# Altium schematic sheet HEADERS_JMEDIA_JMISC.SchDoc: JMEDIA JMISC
size A3; Author: Silvio Navaretti; CompanyName: ARDUINO; DrawnBy: Silvio Navaretti; Engineer: Silvio Navaretti; Organization: ARDUINO; SheetNumber: 21; SheetTotal: 51; RevAuthor: Silvio Navaretti
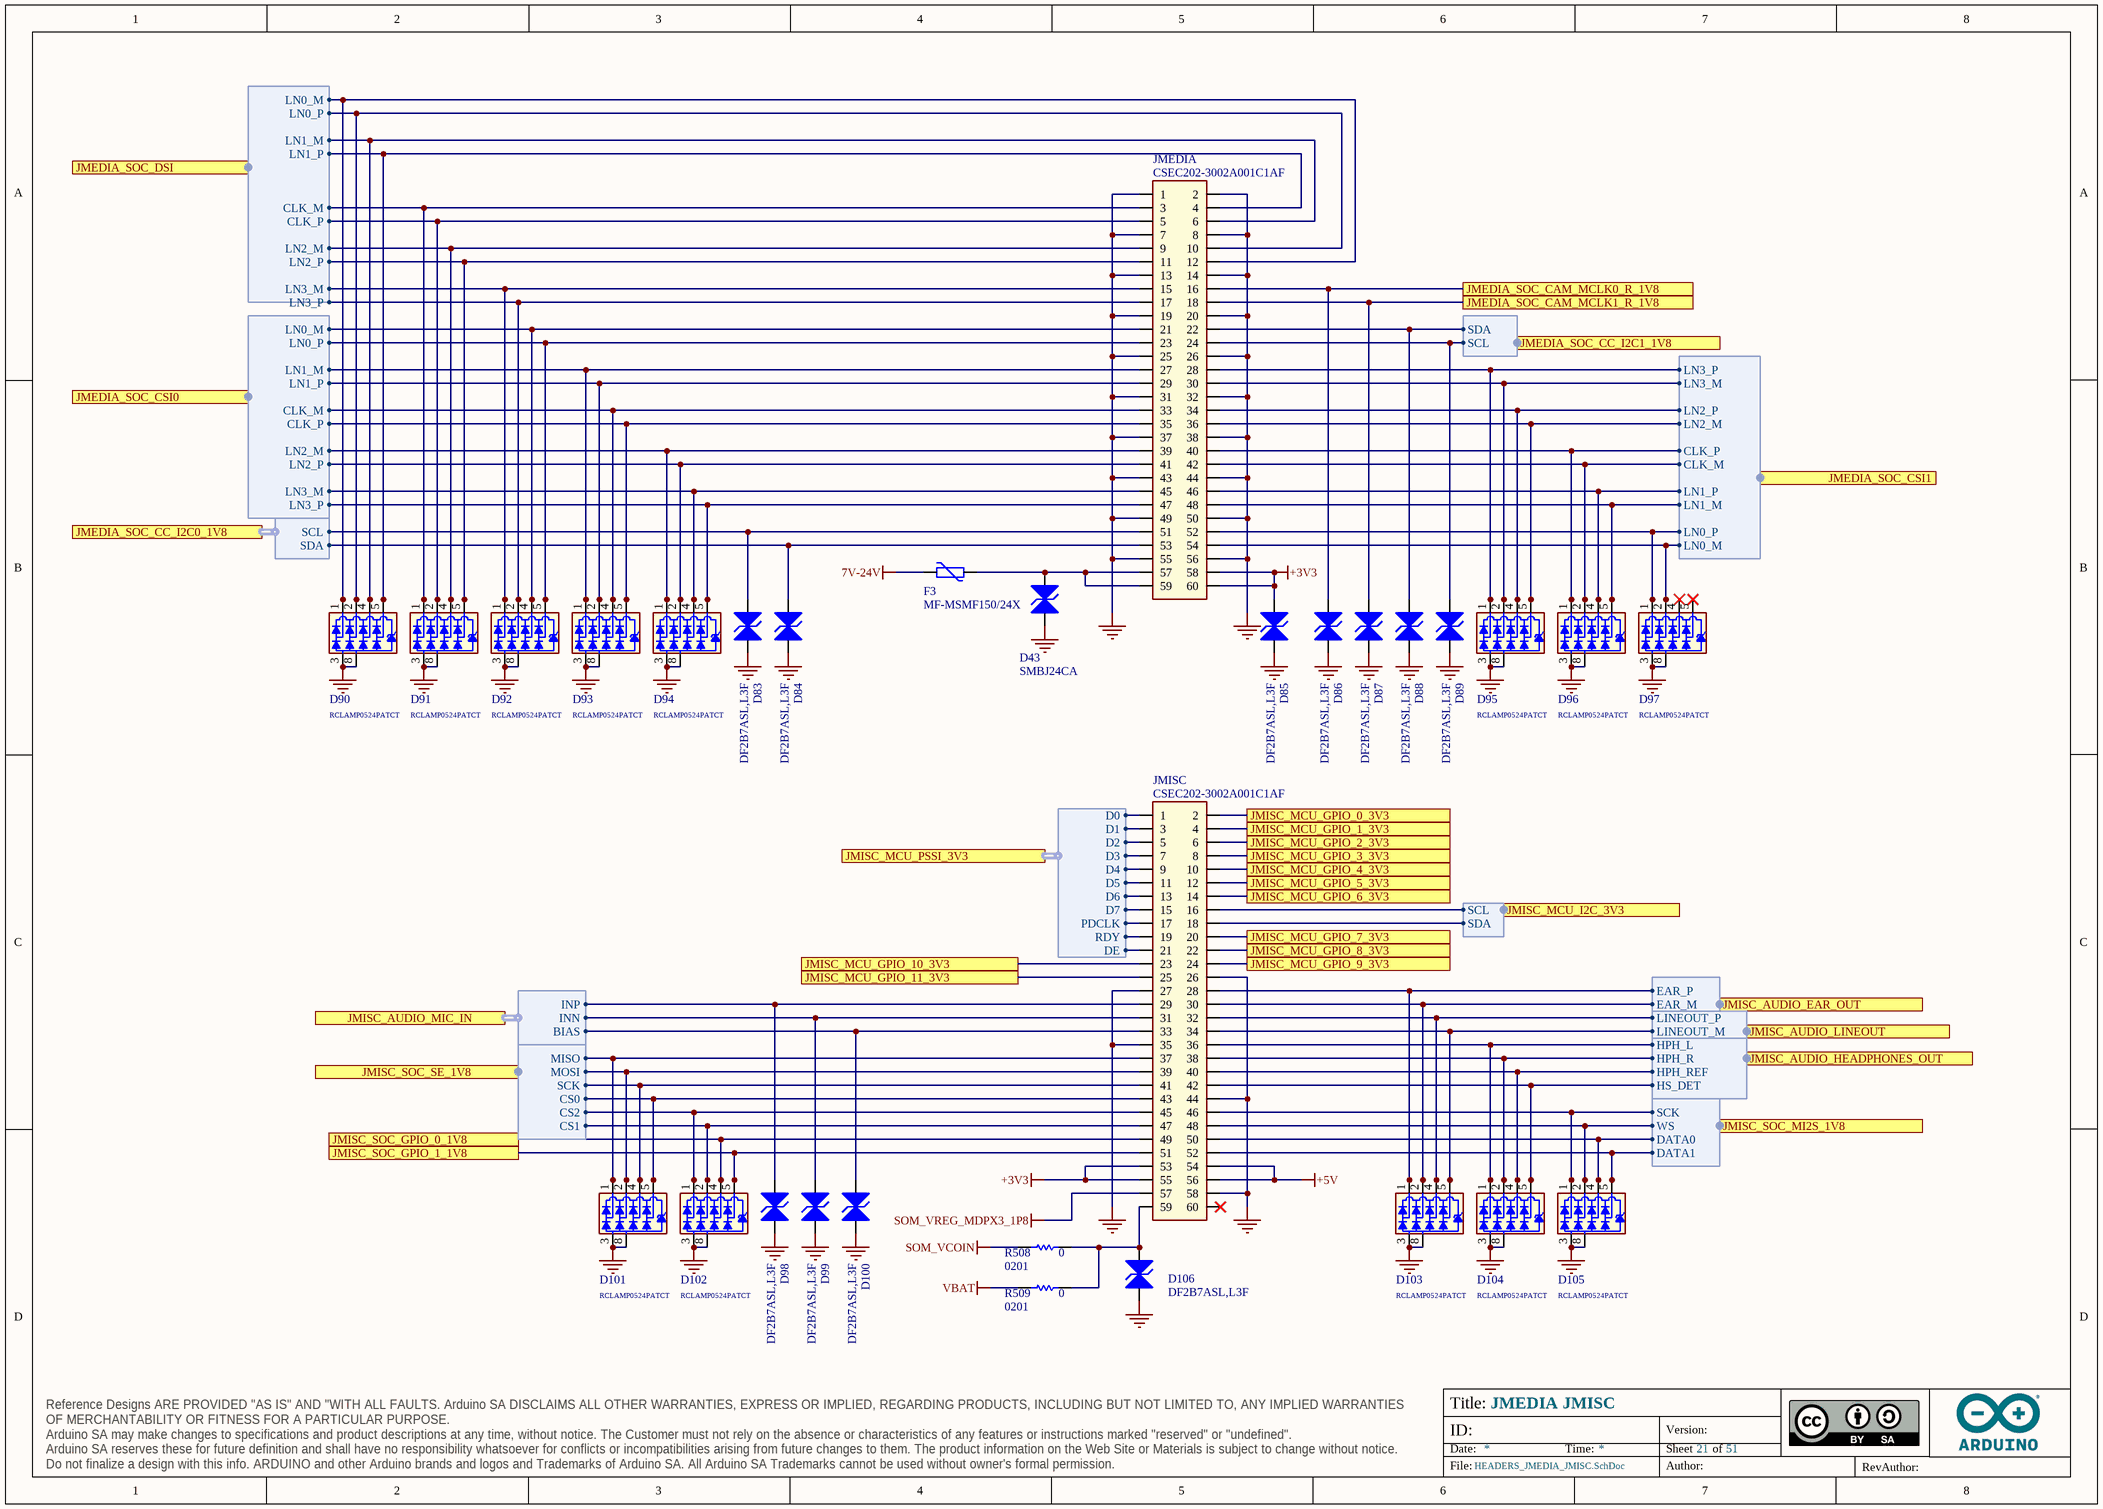
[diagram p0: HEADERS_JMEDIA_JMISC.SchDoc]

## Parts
D43  SMBJ24CA  [SMB_NOPOLARITY]
D83  DF2B7ASL,L3F  [DF2B7ASL,L3F]
D84  DF2B7ASL,L3F  [DF2B7ASL,L3F]
D85  DF2B7ASL,L3F  [DF2B7ASL,L3F]
D86  DF2B7ASL,L3F  [DF2B7ASL,L3F]
D87  DF2B7ASL,L3F  [DF2B7ASL,L3F]
D88  DF2B7ASL,L3F  [DF2B7ASL,L3F]
D89  DF2B7ASL,L3F  [DF2B7ASL,L3F]
D90  RCLAMP0524PATCT  [SLP2510P8]
D91  RCLAMP0524PATCT  [SLP2510P8]
D92  RCLAMP0524PATCT  [SLP2510P8]
D93  RCLAMP0524PATCT  [SLP2510P8]
D94  RCLAMP0524PATCT  [SLP2510P8]
D95  RCLAMP0524PATCT  [SLP2510P8]
D96  RCLAMP0524PATCT  [SLP2510P8]
D97  RCLAMP0524PATCT  [SLP2510P8]
D98  DF2B7ASL,L3F  [DF2B7ASL,L3F]
D99  DF2B7ASL,L3F  [DF2B7ASL,L3F]
D100  DF2B7ASL,L3F  [DF2B7ASL,L3F]
D101  RCLAMP0524PATCT  [SLP2510P8]
D102  RCLAMP0524PATCT  [SLP2510P8]
D103  RCLAMP0524PATCT  [SLP2510P8]
D104  RCLAMP0524PATCT  [SLP2510P8]
D105  RCLAMP0524PATCT  [SLP2510P8]
D106  DF2B7ASL,L3F  [DF2B7ASL,L3F]
F3  MF-MSMF150/24X  [1812]
JMEDIA  CSEC202-3002A001C1AF  [CSEC202-3002A001C1AF]
JMISC  CSEC202-3002A001C1AF  [CSEC202-3002A001C1AF]
R508  value 0  Case Code (Imperial): 0201  [RES-0201]  (hidden comment: CRCW02010000Z0ED)
R509  value 0  Case Code (Imperial): 0201  [RES-0201]  (hidden comment: CRCW02010000Z0ED)

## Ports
JMEDIA_SOC_CAM_MCLK0_R_1V8, JMEDIA_SOC_CAM_MCLK1_R_1V8, JMEDIA_SOC_CC_I2C0_1V8 (harness I2C), JMEDIA_SOC_CC_I2C1_1V8 (harness I2C), JMEDIA_SOC_CSI0 (harness MIPI_4LANES), JMEDIA_SOC_CSI1 (harness MIPI_4LANES), JMEDIA_SOC_DSI (harness MIPI_4LANES), JMISC_AUDIO_EAR_OUT (harness EAT), JMISC_AUDIO_HEADPHONES_OUT (harness HEADPHONES), JMISC_AUDIO_LINEOUT (harness LINEOUT), JMISC_AUDIO_MIC_IN (harness MIC), JMISC_MCU_GPIO_0_3V3, JMISC_MCU_GPIO_1_3V3, JMISC_MCU_GPIO_2_3V3, JMISC_MCU_GPIO_3_3V3, JMISC_MCU_GPIO_4_3V3, JMISC_MCU_GPIO_5_3V3, JMISC_MCU_GPIO_6_3V3, JMISC_MCU_GPIO_7_3V3, JMISC_MCU_GPIO_8_3V3, JMISC_MCU_GPIO_9_3V3, JMISC_MCU_GPIO_10_3V3, JMISC_MCU_GPIO_11_3V3, JMISC_MCU_I2C_3V3 (harness I2C), JMISC_MCU_PSSI_3V3 (harness PSSI), JMISC_SOC_GPIO_0_1V8, JMISC_SOC_GPIO_1_1V8, JMISC_SOC_MI2S_1V8 (harness SOM_MD_I2S), JMISC_SOC_SE_1V8 (harness SOM_MD_SPI_3CS)

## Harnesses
MIPI_4LANES: LN3_M, LN2_M, LN2_P, LN0_M, LN0_P, CLK_M, CLK_P, LN1_M, LN1_P, LN3_P
I2C: SDA, SCL
EAT: EAR_P, EAR_M
MIC: INP, INN, BIAS
LINEOUT: LINEOUT_P, LINEOUT_M
HEADPHONES: HPH_L, HPH_R, HPH_REF, HS_DET
SOM_MD_SPI_3CS: SCK, MISO, MOSI, CS0, CS1, CS2
SOM_MD_I2S: SCK, WS, DATA0, DATA1
PSSI: D0, D1, D2, D3, D4, D5, D6, D7, PDCLK, RDY, DE

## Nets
7V-24V: F3.1
+3V3: D85.2(A2) JMEDIA.58 JMEDIA.60 JMISC.53 JMISC.55
+5V: JMISC.54 JMISC.56
GND: D43.1(A1) D83.1(A1) D84.1(A1) D85.1(A1) D86.1(A1) D87.1(A1) D88.1(A1) D89.1(A1) D90.3 D90.8 D91.3 D91.8 D92.3 D92.8 D93.3 D93.8 D94.3 D94.8 D95.3 D95.8 D96.3 D96.8 D97.3 D97.8 D98.1(A1) D99.1(A1) D100.1(A1) D101.3 D101.8 D102.3 D102.8 D103.3 D103.8 D104.3 D104.8 D105.3 D105.8 D106.1(A1) JMEDIA.1 JMEDIA.2 JMEDIA.7 JMEDIA.8 JMEDIA.13 JMEDIA.14 JMEDIA.19 JMEDIA.20 JMEDIA.25 JMEDIA.26 JMEDIA.31 JMEDIA.32 JMEDIA.37 JMEDIA.38 JMEDIA.43 JMEDIA.44 JMEDIA.49 JMEDIA.50 JMEDIA.55 JMEDIA.56 JMISC.26 JMISC.27 JMISC.35 JMISC.44 JMISC.58
SOM_VCOIN: R508.2
SOM_VREG_MDPX3_1P8: JMISC.57
VBAT: R509.2
JMEDIA_SOC_CAM_MCLK0_R_1V8: D86.2(A2) JMEDIA.16 ; port JMEDIA_SOC_CAM_MCLK0_R_1V8
JMEDIA_SOC_CAM_MCLK1_R_1V8: D87.2(A2) JMEDIA.18 ; port JMEDIA_SOC_CAM_MCLK1_R_1V8
JMISC_MCU_GPIO_0_3V3: JMISC.2 ; port JMISC_MCU_GPIO_0_3V3
JMISC_MCU_GPIO_1_3V3: JMISC.4 ; port JMISC_MCU_GPIO_1_3V3
JMISC_MCU_GPIO_2_3V3: JMISC.6 ; port JMISC_MCU_GPIO_2_3V3
JMISC_MCU_GPIO_3_3V3: JMISC.8 ; port JMISC_MCU_GPIO_3_3V3
JMISC_MCU_GPIO_4_3V3: JMISC.10 ; port JMISC_MCU_GPIO_4_3V3
JMISC_MCU_GPIO_5_3V3: JMISC.12 ; port JMISC_MCU_GPIO_5_3V3
JMISC_MCU_GPIO_6_3V3: JMISC.14 ; port JMISC_MCU_GPIO_6_3V3
JMISC_MCU_GPIO_7_3V3: JMISC.20 ; port JMISC_MCU_GPIO_7_3V3
JMISC_MCU_GPIO_8_3V3: JMISC.22 ; port JMISC_MCU_GPIO_8_3V3
JMISC_MCU_GPIO_9_3V3: JMISC.24 ; port JMISC_MCU_GPIO_9_3V3
JMISC_MCU_GPIO_10_3V3: JMISC.23 ; port JMISC_MCU_GPIO_10_3V3
JMISC_MCU_GPIO_11_3V3: JMISC.25 ; port JMISC_MCU_GPIO_11_3V3
JMISC_SOC_GPIO_0_1V8: D102.4 D102.7 JMISC.49 ; port JMISC_SOC_GPIO_0_1V8
JMISC_SOC_GPIO_1_1V8: D102.5 D102.6 JMISC.51 ; port JMISC_SOC_GPIO_1_1V8
NetD43_2: D43.2(A2) F3.2 JMEDIA.57 JMEDIA.59
NetD83_2: D83.2(A2) JMEDIA.51 ; port JMEDIA_SOC_CC_I2C0_1V8.SCL
NetD84_2: D84.2(A2) JMEDIA.53 ; port JMEDIA_SOC_CC_I2C0_1V8.SDA
NetD88_2: D88.2(A2) JMEDIA.22 ; port JMEDIA_SOC_CC_I2C1_1V8.SDA
NetD89_2: D89.2(A2) JMEDIA.24 ; port JMEDIA_SOC_CC_I2C1_1V8.SCL
NetD90_1: D90.1 D90.10 JMEDIA.12 ; port JMEDIA_SOC_DSI.LN0_M
NetD90_2: D90.2 D90.9 JMEDIA.10 ; port JMEDIA_SOC_DSI.LN0_P
NetD90_4: D90.4 D90.7 JMEDIA.6 ; port JMEDIA_SOC_DSI.LN1_M
NetD90_5: D90.5 D90.6 JMEDIA.4 ; port JMEDIA_SOC_DSI.LN1_P
NetD91_1: D91.1 D91.10 JMEDIA.3 ; port JMEDIA_SOC_DSI.CLK_M
NetD91_2: D91.2 D91.9 JMEDIA.5 ; port JMEDIA_SOC_DSI.CLK_P
NetD91_4: D91.4 D91.7 JMEDIA.9 ; port JMEDIA_SOC_DSI.LN2_M
NetD91_5: D91.5 D91.6 JMEDIA.11 ; port JMEDIA_SOC_DSI.LN2_P
NetD92_1: D92.1 D92.10 JMEDIA.15 ; port JMEDIA_SOC_DSI.LN3_M
NetD92_2: D92.2 D92.9 JMEDIA.17 ; port JMEDIA_SOC_DSI.LN3_P
NetD92_4: D92.4 D92.7 JMEDIA.21 ; port JMEDIA_SOC_CSI0.LN0_M
NetD92_5: D92.5 D92.6 JMEDIA.23 ; port JMEDIA_SOC_CSI0.LN0_P
NetD93_1: D93.1 D93.10 JMEDIA.27 ; port JMEDIA_SOC_CSI0.LN1_M
NetD93_2: D93.2 D93.9 JMEDIA.29 ; port JMEDIA_SOC_CSI0.LN1_P
NetD93_4: D93.4 D93.7 JMEDIA.33 ; port JMEDIA_SOC_CSI0.CLK_M
NetD93_5: D93.5 D93.6 JMEDIA.35 ; port JMEDIA_SOC_CSI0.CLK_P
NetD94_1: D94.1 D94.10 JMEDIA.39 ; port JMEDIA_SOC_CSI0.LN2_M
NetD94_2: D94.2 D94.9 JMEDIA.41 ; port JMEDIA_SOC_CSI0.LN2_P
NetD94_4: D94.4 D94.7 JMEDIA.45 ; port JMEDIA_SOC_CSI0.LN3_M
NetD94_5: D94.5 D94.6 JMEDIA.47 ; port JMEDIA_SOC_CSI0.LN3_P
NetD95_1: D95.1 D95.10 JMEDIA.28 ; port JMEDIA_SOC_CSI1.LN3_P
NetD95_2: D95.2 D95.9 JMEDIA.30 ; port JMEDIA_SOC_CSI1.LN3_M
NetD95_4: D95.4 D95.7 JMEDIA.34 ; port JMEDIA_SOC_CSI1.LN2_P
NetD95_5: D95.5 D95.6 JMEDIA.36 ; port JMEDIA_SOC_CSI1.LN2_M
NetD96_1: D96.1 D96.10 JMEDIA.40 ; port JMEDIA_SOC_CSI1.CLK_P
NetD96_2: D96.2 D96.9 JMEDIA.42 ; port JMEDIA_SOC_CSI1.CLK_M
NetD96_4: D96.4 D96.7 JMEDIA.46 ; port JMEDIA_SOC_CSI1.LN1_P
NetD96_5: D96.5 D96.6 JMEDIA.48 ; port JMEDIA_SOC_CSI1.LN1_M
NetD97_1: D97.1 D97.10 JMEDIA.52 ; port JMEDIA_SOC_CSI1.LN0_P
NetD97_2: D97.2 D97.9 JMEDIA.54 ; port JMEDIA_SOC_CSI1.LN0_M
NetD97_4: D97.4 D97.7
NetD97_5: D97.5 D97.6
NetD98_2: D98.2(A2) JMISC.29 ; port JMISC_AUDIO_MIC_IN.INP
NetD99_2: D99.2(A2) JMISC.31 ; port JMISC_AUDIO_MIC_IN.INN
NetD100_2: D100.2(A2) JMISC.33 ; port JMISC_AUDIO_MIC_IN.BIAS
NetD101_1: D101.1 D101.10 JMISC.37 ; port JMISC_SOC_SE_1V8.MISO
NetD101_2: D101.2 D101.9 JMISC.39 ; port JMISC_SOC_SE_1V8.MOSI
NetD101_4: D101.4 D101.7 JMISC.41 ; port JMISC_SOC_SE_1V8.SCK
NetD101_5: D101.5 D101.6 JMISC.43 ; port JMISC_SOC_SE_1V8.CS0
NetD102_1: D102.1 D102.10 JMISC.45 ; port JMISC_SOC_SE_1V8.CS2
NetD102_2: D102.2 D102.9 JMISC.47 ; port JMISC_SOC_SE_1V8.CS1
NetD103_1: D103.1 D103.10 JMISC.28 ; port JMISC_AUDIO_EAR_OUT.EAR_P
NetD103_2: D103.2 D103.9 JMISC.30 ; port JMISC_AUDIO_EAR_OUT.EAR_M
NetD103_4: D103.4 D103.7 JMISC.32 ; port JMISC_AUDIO_LINEOUT.LINEOUT_P
NetD103_5: D103.5 D103.6 JMISC.34 ; port JMISC_AUDIO_LINEOUT.LINEOUT_M
NetD104_1: D104.1 D104.10 JMISC.36 ; port JMISC_AUDIO_HEADPHONES_OUT.HPH_L
NetD104_2: D104.2 D104.9 JMISC.38 ; port JMISC_AUDIO_HEADPHONES_OUT.HPH_R
NetD104_4: D104.4 D104.7 JMISC.40 ; port JMISC_AUDIO_HEADPHONES_OUT.HPH_REF
NetD104_5: D104.5 D104.6 JMISC.42 ; port JMISC_AUDIO_HEADPHONES_OUT.HS_DET
NetD105_1: D105.1 D105.10 JMISC.46 ; port JMISC_SOC_MI2S_1V8.SCK
NetD105_2: D105.2 D105.9 JMISC.48 ; port JMISC_SOC_MI2S_1V8.WS
NetD105_4: D105.4 D105.7 JMISC.50 ; port JMISC_SOC_MI2S_1V8.DATA0
NetD105_5: D105.5 D105.6 JMISC.52 ; port JMISC_SOC_MI2S_1V8.DATA1
NetD106_2: D106.2(A2) JMISC.59 R508.1 R509.1
NetJMISC_1: JMISC.1 ; port JMISC_MCU_PSSI_3V3.D0
NetJMISC_3: JMISC.3 ; port JMISC_MCU_PSSI_3V3.D1
NetJMISC_5: JMISC.5 ; port JMISC_MCU_PSSI_3V3.D2
NetJMISC_7: JMISC.7 ; port JMISC_MCU_PSSI_3V3.D3
NetJMISC_9: JMISC.9 ; port JMISC_MCU_PSSI_3V3.D4
NetJMISC_11: JMISC.11 ; port JMISC_MCU_PSSI_3V3.D5
NetJMISC_13: JMISC.13 ; port JMISC_MCU_PSSI_3V3.D6
NetJMISC_15: JMISC.15 ; port JMISC_MCU_PSSI_3V3.D7
NetJMISC_16: JMISC.16 ; port JMISC_MCU_I2C_3V3.SCL
NetJMISC_17: JMISC.17 ; port JMISC_MCU_PSSI_3V3.PDCLK
NetJMISC_18: JMISC.18 ; port JMISC_MCU_I2C_3V3.SDA
NetJMISC_19: JMISC.19 ; port JMISC_MCU_PSSI_3V3.RDY
NetJMISC_21: JMISC.21 ; port JMISC_MCU_PSSI_3V3.DE

Not connected (* = marked no-connect by the designer): JMISC 60*

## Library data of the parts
D43 = D0070-A.2: TVS BIDIRECTIONAL SMD Vr 24V, Vbr min 26.7V, 600W, SMB; Manufacturer: Littlefuse; V(BR) Typ (V): 26.7; Code Arduino: D0070
D83-D89 D98-D100 D106 = D0099-5: TVS BIDIRECTIONAL SMD Vr 5.5V, Vbr min 5.8V, 0.62x0.32mm; Manufacturer: TOSHIBA; Vforward max: 0V; Ireverse max: 1µA; Power max: 80W; Code Arduino: D0099; Vreverse max: 20V
D90-D97 D101-D105 = D0097-A.6: TVS UNIDIRECTIONAL 4CH 0.8pF 5V SLP2510P8 10-pin 2.5x1.0x0.58mm; Manufacturer: SEMTECH; Code Arduino: D0097; Device Type: ESD protection
F3 = P0019-A.1: PTC Ihold 1.5A Itrip 3A 24V 1812; Manufacturer: Bourns; Code Arduino: P0019
JMEDIA JMISC = J0565-A.3: CONN HEADER FEMALE VERTICAL SMD 1.27mm 2x30 POS heigth 4.4mm; Manufacturer: Greenconn; Code Arduino: J0565
R508 R509 = R0140-A.21: RES CHIP 0201 0R; Manufacturer: Vishay; Temperature coefficient: 0ppm; Code Arduino: R0140; Power: 50mW; Tolerance: 0%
